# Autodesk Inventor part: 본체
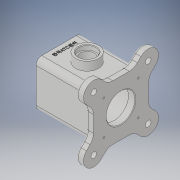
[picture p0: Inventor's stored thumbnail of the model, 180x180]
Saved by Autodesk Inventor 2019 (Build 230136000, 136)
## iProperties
Created: 2021-01
Part Number: 본체
Material: 일반
Document SubType Name: Modeling
Designer: 3dpro21
Density: 1 g/cm^3
Appearance: 기본값
Author: 3dpro21
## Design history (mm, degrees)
sketch "스케치1"
  geometry: L1 (-40, 40)-(40, 40); L2 (40, 40)-(40, -40); L3 (40, -40)-(-40, -40); L4 (-40, -40)-(-40, 40); 3 further points
  constraints: 8 end point, 2 midpoint, 2 parallel, 1 horizontal, 1 horizontal alignment, 1 perpendicular, 1 vertical alignment
  dimensions: "d0" = 80 distance of L2.end L3.end; "d1" = 80 distance of L1.end L2.end
extrude "돌출1" new body sketch "스케치1" stored distance "d2" = 108; taper "d3" = 0 deg
sketch "스케치2"
  geometry: C1 r 35 at (0, 0); 1 further point
  constraints: 1 centre point, 1 coincident
  dimensions: "d4" = 70 diameter of C1
extrude "돌출2" cut sketch "스케치2" stored distance "d5" = 84; taper "d6" = 0 deg
sketch "스케치3"
  geometry: C1 r 25 at (0, 0); 1 further point
  constraints: 1 centre point, 1 coincident
  dimensions: "d7" = 50 diameter of C1
extrude "돌출3" cut sketch "스케치3" distance "d8" = 108; taper "d9" = 0 deg
sketch "스케치4"
  geometry: L1 (-48, -48)-(48, -48); L2 (48, -48)-(48, 48); L3 (48, 48)-(-48, 48); L4 (-48, 48)-(-48, -48); L5 (-48, -48)-(48, 48); L6 (48, -48)-(-48, 48); C1 r 25 at (0, 0) reference; 1 further point
  constraints: 12 end point, 2 midpoint, 2 parallel, 1 horizontal, 1 perpendicular
  dimensions: "d10" = 96 distance of L3.end L2.end; "d11" = 96 distance of L2.end L1.end
extrude "돌출4" join sketch "스케치4" distance "d12" = 12; taper "d13" = 0 deg
sketch "스케치5" dims "d50" = 134
  geometry: L1 (0, 0)-(0, 48); L2 (-48, 48)-(48, 48) reference; L3 (0, 0)-(47.376, 47.376); L4 (48, -48)-(48, 48) reference; L5 (34.648, 60.104)-(22.544, 48); L6 (60.104, 34.648)-(48, 22.544); L7 (48, 48)-(-48, 48) reference; L8 (22.544, 48)-(48, 22.544); A1 r 18 centre (47.376, 47.376) between (34.648, 60.104) and (60.104, 34.648); 1 further point
  constraints: 10 end point, 2 point on circle, 2 point on line, 2 tangent, 1 centre point, 1 coincident, 1 midpoint, 1 parallel, 3 other
  dimensions: "d14" = 36 diameter of A1; "d51" = 45 deg angle of L3 L1; "d59" = 45 deg angle of L1 L5
extrude "돌출5" join sketch "스케치5" distance "d15" = 12; taper "d16" = 0 deg
sketch "스케치8"
  geometry: L1 (96, 105.376)-(96, 100.104) reference; L2 (108, 62.544)-(108, -8) reference; C1 r 20 at (49, 40); 7 further points
  constraints: 1 centre point, 1 horizontal alignment, 1 point on line
  dimensions: "d27" = 40 diameter of C1; "d28" = 47 distance from line of L1 C1.centre
extrude "돌출6" join sketch "스케치8" distance "d29" = 15; taper "d30" = 0 deg
sketch "스케치9"
  geometry: C1 r 20 at (0, 0) reference; 2 further points
  constraints: 1 coincident
hole "구멍2" sketch "스케치9" at (0, 0) diameter "d31" = 25; stored, may be unused: countersink angle "d35" = 90 deg, drill point angle "d37" = 0 deg; dims "d32" = 8, "d33" = 30, "d34" = 8, "d36" = 11.8
fillet "모깎기2" dims "d39" = 10
chamfer "모따기1" distance "d41" = 1; stored, may be unused: second distance "d42" = 2, angle "d43" = 45 deg
chamfer "모따기2" distance "d44" = 1; stored, may be unused: second distance "d45" = 2, angle "d46" = 45 deg
chamfer "모따기3" distance "d47" = 1; stored, may be unused: second distance "d48" = 2, angle "d49" = 45 deg
sketch "스케치12"
  geometry: A1 r 18 centre (-47.376, 47.376) between (-34.648, 60.104) and (-60.104, 34.648) reference; 2 further points
  constraints: 1 coincident
hole "구멍5" sketch "스케치12" at (-47.376, 47.376) diameter "d71" = 10; stored, may be unused: countersink angle "d75" = 90 deg, drill point angle "d77" = 118 deg; dims "d72" = 8, "d73" = 18, "d74" = 4, "d76" = 10
fillet "모깎기4" dims "d81" = 20
fillet "모깎기5" dims "d82" = 3
fillet "모깎기6" dims "d83" = 3
sketch "스케치13"
  geometry: 2 further points
  dimensions: "d84" = 30 horizontal distance of point (0, 0) point (30, 30); "d85" = 30 horizontal distance of point (0, 0) point (30, 30)
hole "구멍6" sketch "스케치13" at (30, 30) diameter "d86" = 3.242; stored, may be unused: countersink angle "d90" = 90 deg, drill point angle "d92" = 118 deg; dims "d87" = 8, "d88" = 18, "d89" = 4, "d91" = 10
sketch "스케치14"
  geometry: L1 (0, 0)-(0, 60) reference; L2 (93, 65)-(93, -5) reference; L3 (15, -5)-(15, 65) reference; C1 r 20 at (49, 30) reference; 3 further points
  constraints: 1 horizontal alignment, 2 other
  dimensions: "d96" = 10 distance from line of L1 point (10, 30)
feature "엠보싱1" sketch "스케치14" dims "d0" = 80, "d1" = 80, "d10" = 96, "d11" = 96, "d97" = 0.5, "d98" = 0
sketch "스케치15"
  geometry: 2 further points
  dimensions: "d99" = 30 horizontal distance of point (-30, -30) point (0, 0); "d100" = 30 horizontal distance of point (0, 0) point (-30, -30)
hole "구멍7" sketch "스케치15" at (-30, -30) diameter "d101" = 3.242; stored, may be unused: countersink angle "d105" = 90 deg, drill point angle "d107" = 118 deg; dims "d102" = 8, "d103" = 18, "d104" = 4, "d106" = 10
node "솔리드1"
pattern_circular "원형 패턴3" dims angle "d79" = 360 deg
pattern_circular "원형 패턴4" dims angle "d94" = 360 deg
pattern_circular "원형 패턴5" dims angle "d109" = 360 deg
node "투영된 루프2"
